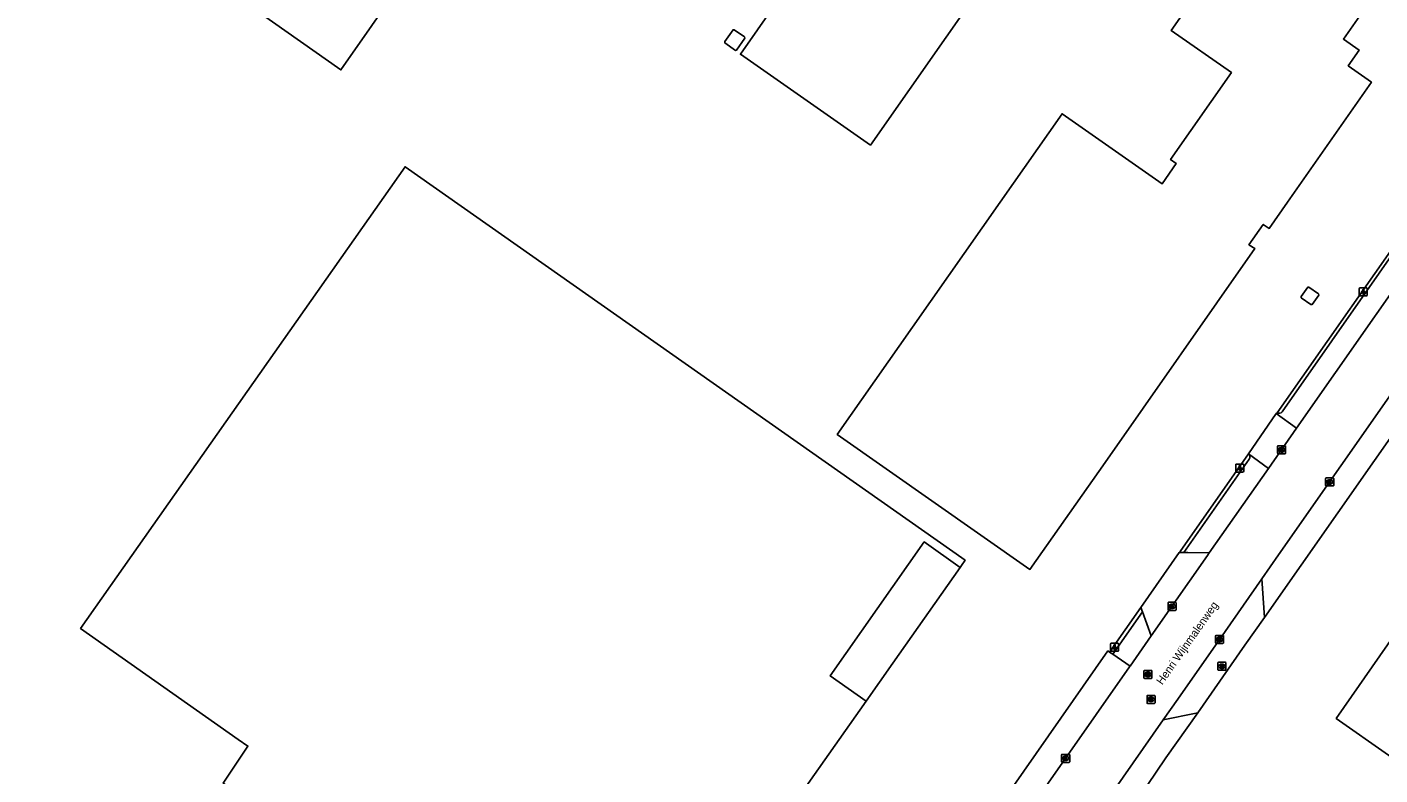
# Model space of a CAD drawing. Extents: x 155018 to 156648, y 383980 to 385733.
# Drawn here: x 155240.7 to 155409.7, y 384928.5 to 385021.9 of the extents above; entities that cross this region are included whole.
import ezdxf

# ---------------------------------------------------------------- set-up
doc = ezdxf.new("R2010")
doc.units = 0
for name, color, linetype in [('IMGEO_Brandkraan', 7, 'Continuous'), ('IMGEO_Hek', 7, 'Continuous'), ('IMGEO_Kolk', 7, 'Continuous'), ('IMGEO_Lichtpunt', 7, 'Continuous'), ('IMGEO_Openbare_ruimte_label', 7, 'Continuous'), ('IMGEO_Pand', 7, 'Continuous'), ('IMGEO_Pand_overbouw', 7, 'Continuous'), ('IMGEO_Parkeervlak_open', 7, 'Continuous'), ('IMGEO_Rijbaan_lokaal_gesloten', 7, 'Continuous'), ('IMGEO_Rijbaan_lokaal_open', 7, 'Continuous'), ('IMGEO_Rioolput', 7, 'Continuous'), ('IMGEO_Voetpad_open', 7, 'Continuous')]:
    doc.layers.add(name, color=color, linetype=linetype)

msp = doc.modelspace()

# ---------------------------------------------------------------- linework, layer by layer
at = {"layer": 'IMGEO_Brandkraan'}
for p, q in [((155389.49, 384941.61), (155389.49, 384942.47)), ((155389.56, 384942.54), (155390.42, 384942.54)), ((155389.98, 384942.32), (155390, 384942.32)), ((155390.49, 384942.47), (155390.49, 384941.61)), ((155390.42, 384941.54), (155389.56, 384941.54)), ((155390, 384941.76), (155389.98, 384941.76))]:
    msp.add_line(p, q, dxfattribs=at)
for points in [[(155389.49, 384941.61), (155389.49, 384942.47)], [(155389.56, 384942.54), (155390.42, 384942.54)], [(155389.84, 384942.24), (155389.84, 384941.84), (155390.05, 384941.84)], [(155390.07, 384942.24), (155389.84, 384942.24)], [(155390.02, 384942.16), (155389.96, 384942.16), (155389.96, 384942.08)], [(155389.96, 384942.08), (155390.02, 384942.08)], [(155390.03, 384942.01), (155389.96, 384942.01), (155389.96, 384941.92)], [(155389.96, 384941.92), (155390.03, 384941.92)], [(155390.49, 384942.47), (155390.49, 384941.61)], [(155390.42, 384941.54), (155389.56, 384941.54)]]:
    msp.add_lwpolyline(points, dxfattribs=at)
for centre, radius, start, end in [((155389.57, 384942.46), 0.0765, 91.552, 178.448), ((155389.57, 384942.46), 0.0765, 91.552, 178.448), ((155390.02, 384942.12), 0.0379, 267.8285, 90.9355), ((155390.03, 384941.97), 0.0404, 269.8759, 90.5077), ((155390.06, 384942.09), 0.251, 268.6676, 293.5347), ((155390.07, 384942.09), 0.145, 59.4692, 91.5367), ((155390.1, 384942.14), 0.0922, 285.5137, 58.1501), ((155390.1, 384941.95), 0.105, 301.3115, 78.989), ((155390.41, 384942.46), 0.0765, 1.552, 88.448), ((155390.41, 384942.46), 0.0765, 1.552, 88.448), ((155389.57, 384941.61), 0.0765, 181.552, 268.448), ((155389.57, 384941.61), 0.0765, 181.552, 268.448), ((155390.41, 384941.61), 0.0765, 271.552, 358.448), ((155390.41, 384941.61), 0.0765, 271.552, 358.448)]:
    msp.add_arc(centre, radius, start, end, dxfattribs=at)
for centre, major_axis, ratio, start_param, end_param in [((155389.98, 384942.04), (-0.387, 0.002), 0.722429, 4.712389, 7.853982), ((155390, 384942.04), (-0.39, 0.002), 0.717154, 1.570796, 4.712389)]:
    msp.add_ellipse(centre, major_axis=major_axis, ratio=ratio, start_param=start_param, end_param=end_param, dxfattribs=at)
at = {"layer": 'IMGEO_Hek'}
msp.add_lwpolyline([(155360.91, 384922.73), (155375.75, 384943.95)], dxfattribs=at)
at = {"layer": 'IMGEO_Kolk'}
for p, q in [((155396.95, 384968.65), (155396.95, 384969.5)), ((155397.02, 384969.57), (155397.87, 384969.57)), ((155397.43, 384969.35), (155397.46, 384969.35)), ((155397.95, 384969.5), (155397.95, 384968.65)), ((155397.87, 384968.57), (155397.02, 384968.57)), ((155397.46, 384968.79), (155397.43, 384968.79)), ((155402.94, 384964.63), (155402.94, 384965.48)), ((155403.02, 384965.56), (155403.87, 384965.56)), ((155403.95, 384965.48), (155403.95, 384964.63)), ((155403.87, 384964.56), (155403.02, 384964.56)), ((155403.43, 384965.34), (155403.46, 384965.34)), ((155403.45, 384964.78), (155403.43, 384964.78)), ((155383.26, 384949.1), (155383.26, 384949.95)), ((155383.33, 384950.03), (155384.18, 384950.03)), ((155384.18, 384949.02), (155383.33, 384949.02)), ((155383.74, 384949.8), (155383.77, 384949.8)), ((155383.77, 384949.25), (155383.74, 384949.25)), ((155384.26, 384949.95), (155384.26, 384949.1)), ((155389.2, 384944.96), (155389.2, 384945.81)), ((155389.27, 384945.89), (155390.12, 384945.89)), ((155389.69, 384945.67), (155389.71, 384945.67)), ((155390.2, 384945.81), (155390.2, 384944.96)), ((155390.12, 384944.89), (155389.27, 384944.89)), ((155389.71, 384945.11), (155389.68, 384945.11)), ((155369.96, 384930.12), (155369.96, 384930.97)), ((155370.04, 384931.04), (155370.89, 384931.04)), ((155370.89, 384930.04), (155370.04, 384930.04)), ((155370.45, 384930.82), (155370.48, 384930.82)), ((155370.47, 384930.26), (155370.45, 384930.26)), ((155370.97, 384930.97), (155370.97, 384930.12))]:
    msp.add_line(p, q, dxfattribs=at)
for points in [[(155396.95, 384968.65), (155396.95, 384969.5)], [(155397.02, 384969.57), (155397.87, 384969.57)], [(155397.27, 384969.27), (155397.39, 384969.27), (155397.39, 384969.12), (155397.52, 384969.27), (155397.68, 384969.27), (155397.54, 384969.12), (155397.69, 384968.87), (155397.54, 384968.87), (155397.45, 384969.04), (155397.39, 384968.97), (155397.39, 384968.87), (155397.27, 384968.87), (155397.27, 384969.27)], [(155397.95, 384969.5), (155397.95, 384968.65)], [(155397.87, 384968.57), (155397.02, 384968.57)], [(155402.94, 384964.63), (155402.94, 384965.48)], [(155403.02, 384965.56), (155403.87, 384965.56)], [(155403.95, 384965.48), (155403.95, 384964.63)], [(155403.87, 384964.56), (155403.02, 384964.56)], [(155403.26, 384965.26), (155403.39, 384965.26), (155403.39, 384965.11), (155403.52, 384965.26), (155403.68, 384965.26), (155403.54, 384965.11), (155403.69, 384964.86), (155403.54, 384964.86), (155403.45, 384965.02), (155403.39, 384964.96), (155403.39, 384964.86), (155403.26, 384964.86), (155403.26, 384965.26)], [(155383.26, 384949.1), (155383.26, 384949.95)], [(155383.33, 384950.03), (155384.18, 384950.03)], [(155384.18, 384949.02), (155383.33, 384949.02)], [(155383.58, 384949.72), (155383.7, 384949.72), (155383.7, 384949.57), (155383.83, 384949.72), (155383.99, 384949.72), (155383.85, 384949.57), (155384, 384949.32), (155383.85, 384949.32), (155383.76, 384949.49), (155383.7, 384949.42), (155383.7, 384949.32), (155383.58, 384949.32), (155383.58, 384949.72)], [(155384.26, 384949.95), (155384.26, 384949.1)], [(155389.2, 384944.96), (155389.2, 384945.81)], [(155389.27, 384945.89), (155390.12, 384945.89)], [(155389.52, 384945.59), (155389.64, 384945.59), (155389.64, 384945.44), (155389.77, 384945.59), (155389.94, 384945.59), (155389.79, 384945.44), (155389.94, 384945.19), (155389.79, 384945.19), (155389.71, 384945.35), (155389.64, 384945.29), (155389.64, 384945.19), (155389.52, 384945.19), (155389.52, 384945.59)], [(155390.2, 384945.81), (155390.2, 384944.96)], [(155390.12, 384944.89), (155389.27, 384944.89)], [(155369.96, 384930.12), (155369.96, 384930.97)], [(155370.04, 384931.04), (155370.89, 384931.04)], [(155370.89, 384930.04), (155370.04, 384930.04)], [(155370.28, 384930.74), (155370.41, 384930.74), (155370.41, 384930.59), (155370.54, 384930.74), (155370.7, 384930.74), (155370.56, 384930.59), (155370.71, 384930.34), (155370.56, 384930.34), (155370.47, 384930.51), (155370.41, 384930.44), (155370.41, 384930.34), (155370.28, 384930.34), (155370.28, 384930.74)], [(155370.97, 384930.97), (155370.97, 384930.12)]]:
    msp.add_lwpolyline(points, dxfattribs=at)
for centre, start, end in [((155397.02, 384969.5), 91.552, 178.448), ((155397.02, 384969.5), 91.552, 178.448), ((155397.87, 384969.5), 1.552, 88.448), ((155397.87, 384969.5), 1.552, 88.448), ((155397.02, 384968.65), 181.552, 268.448), ((155397.02, 384968.65), 181.552, 268.448), ((155397.87, 384968.65), 271.552, 358.448), ((155397.87, 384968.65), 271.552, 358.448), ((155403.02, 384965.48), 91.552, 178.448), ((155403.02, 384965.48), 91.552, 178.448), ((155403.87, 384965.48), 1.552, 88.448), ((155403.87, 384965.48), 1.552, 88.448), ((155403.02, 384964.63), 181.552, 268.448), ((155403.02, 384964.63), 181.552, 268.448), ((155403.87, 384964.63), 271.552, 358.448), ((155403.87, 384964.63), 271.552, 358.448), ((155383.33, 384949.95), 91.552, 178.448), ((155383.33, 384949.95), 91.552, 178.448), ((155383.33, 384949.1), 181.552, 268.448), ((155383.33, 384949.1), 181.552, 268.448), ((155384.18, 384949.95), 1.552, 88.448), ((155384.18, 384949.95), 1.552, 88.448), ((155384.18, 384949.1), 271.552, 358.448), ((155384.18, 384949.1), 271.552, 358.448), ((155389.27, 384945.81), 91.552, 178.448), ((155389.27, 384945.81), 91.552, 178.448), ((155390.12, 384945.81), 1.552, 88.448), ((155390.12, 384945.81), 1.552, 88.448), ((155389.27, 384944.96), 181.552, 268.448), ((155389.27, 384944.96), 181.552, 268.448), ((155390.12, 384944.96), 271.552, 358.448), ((155390.12, 384944.96), 271.552, 358.448), ((155370.04, 384930.97), 91.552, 178.448), ((155370.04, 384930.97), 91.552, 178.448), ((155370.04, 384930.12), 181.552, 268.448), ((155370.04, 384930.12), 181.552, 268.448), ((155370.89, 384930.97), 1.552, 88.448), ((155370.89, 384930.97), 1.552, 88.448), ((155370.89, 384930.12), 271.552, 358.448), ((155370.89, 384930.12), 271.552, 358.448)]:
    msp.add_arc(centre, 0.0765, start, end, dxfattribs=at)
for centre, major_axis, ratio, start_param, end_param in [((155397.43, 384969.07), (-0.387, 0.002), 0.722429, 4.712389, 7.853982), ((155397.46, 384969.07), (-0.39, 0.002), 0.717154, 1.570796, 4.712389), ((155403.43, 384965.06), (-0.387, 0.002), 0.722429, 4.712389, 7.853982), ((155403.46, 384965.06), (-0.39, 0.002), 0.717154, 1.570796, 4.712389), ((155383.74, 384949.52), (-0.387, 0.002), 0.722429, 4.712389, 7.853982), ((155383.77, 384949.52), (-0.39, 0.002), 0.717154, 1.570796, 4.712389), ((155389.68, 384945.39), (-0.387, 0.002), 0.722429, 4.712389, 7.853982), ((155389.71, 384945.39), (-0.39, 0.002), 0.717154, 1.570796, 4.712389), ((155370.45, 384930.54), (-0.387, 0.002), 0.722429, 4.712389, 7.853982), ((155370.48, 384930.54), (-0.39, 0.002), 0.717154, 1.570796, 4.712389)]:
    msp.add_ellipse(centre, major_axis=major_axis, ratio=ratio, start_param=start_param, end_param=end_param, dxfattribs=at)
at = {"layer": 'IMGEO_Lichtpunt'}
for p, q in [((155407.15, 384989.2), (155407.15, 384988.4)), ((155407.15, 384989.2), (155407.15, 384988.4)), ((155408.05, 384989.3), (155407.24, 384989.3)), ((155408.05, 384989.3), (155407.24, 384989.3)), ((155408.14, 384988.4), (155408.14, 384989.2)), ((155408.14, 384988.4), (155408.14, 384989.2)), ((155407.24, 384988.3), (155408.05, 384988.3)), ((155407.24, 384988.3), (155408.05, 384988.3)), ((155391.72, 384967.2), (155391.72, 384966.4)), ((155391.72, 384967.2), (155391.72, 384966.4)), ((155392.62, 384967.3), (155391.81, 384967.3)), ((155392.62, 384967.3), (155391.81, 384967.3)), ((155392.71, 384966.4), (155392.71, 384967.2)), ((155392.71, 384966.4), (155392.71, 384967.2)), ((155391.81, 384966.3), (155392.62, 384966.3)), ((155391.81, 384966.3), (155392.62, 384966.3)), ((155376.07, 384944.82), (155376.07, 384944.01)), ((155376.07, 384944.82), (155376.07, 384944.01)), ((155376.97, 384944.91), (155376.17, 384944.91)), ((155376.97, 384944.91), (155376.17, 384944.91)), ((155376.17, 384943.91), (155376.97, 384943.91)), ((155376.17, 384943.91), (155376.97, 384943.91)), ((155377.07, 384944.01), (155377.07, 384944.82)), ((155377.07, 384944.01), (155377.07, 384944.82))]:
    msp.add_line(p, q, dxfattribs=at)
for points in [[(155407.52, 384988.87), (155407.56, 384988.84), (155407.37, 384988.58), (155407.33, 384988.61), (155407.52, 384988.87)], [(155407.62, 384988.82), (155407.67, 384988.82), (155407.67, 384988.5), (155407.62, 384988.5), (155407.62, 384988.82)], [(155407.73, 384988.84), (155407.77, 384988.87), (155407.96, 384988.6), (155407.92, 384988.58), (155407.73, 384988.84)], [(155392.09, 384966.87), (155392.13, 384966.84), (155391.94, 384966.58), (155391.9, 384966.61), (155392.09, 384966.87)], [(155392.19, 384966.82), (155392.24, 384966.82), (155392.24, 384966.5), (155392.19, 384966.5), (155392.19, 384966.82)], [(155392.3, 384966.84), (155392.34, 384966.87), (155392.53, 384966.6), (155392.49, 384966.58), (155392.3, 384966.84)], [(155376.45, 384944.48), (155376.48, 384944.45), (155376.3, 384944.19), (155376.26, 384944.22), (155376.45, 384944.48)], [(155376.55, 384944.43), (155376.59, 384944.43), (155376.59, 384944.11), (155376.55, 384944.11), (155376.55, 384944.43)], [(155376.66, 384944.45), (155376.7, 384944.48), (155376.88, 384944.22), (155376.84, 384944.19), (155376.66, 384944.45)]]:
    msp.add_lwpolyline(points, dxfattribs=at)
for centre in [(155407.65, 384989), (155392.22, 384967), (155376.57, 384944.61)]:
    msp.add_circle(centre, 0.0994, dxfattribs=at)
for centre, start, end in [((155407.24, 384989.2), 90, 180), ((155407.24, 384989.2), 90, 180), ((155408.05, 384989.2), 0, 90), ((155408.05, 384989.2), 0, 90), ((155407.24, 384988.4), 180, 270), ((155407.24, 384988.4), 180, 270), ((155408.05, 384988.4), 270, 0), ((155408.05, 384988.4), 270, 360), ((155391.81, 384967.2), 90, 180), ((155391.81, 384967.2), 90, 180), ((155392.62, 384967.2), 0, 90), ((155392.62, 384967.2), 0, 90), ((155391.81, 384966.4), 180, 270), ((155391.81, 384966.4), 180, 270), ((155392.62, 384966.4), 270, 0), ((155392.62, 384966.4), 270, 360), ((155376.17, 384944.82), 90, 180), ((155376.17, 384944.82), 90, 180), ((155376.17, 384944.01), 180, 270), ((155376.17, 384944.01), 180, 270), ((155376.97, 384944.82), 0, 90), ((155376.97, 384944.82), 0, 90), ((155376.97, 384944.01), 270, 0), ((155376.97, 384944.01), 270, 360)]:
    msp.add_arc(centre, 0.0946, start, end, dxfattribs=at)
at = {"layer": 'IMGEO_Pand'}
for points in [[(155360.4, 385027.59), (155371.25, 385043.14), (155373.67, 385046.6), (155373.68, 385046.71), (155374.05, 385047.29), (155357.87, 385058.61), (155357.47, 385058.02), (155335.4, 385073.46), (155332.53, 385069.36), (155322.01, 385054.44), (155322.2, 385054.3), (155344.14, 385038.95), (155329.83, 385018.48), (155346.07, 385007.13), (155360.4, 385027.59)], [(155240.71, 385044.07), (155279.93, 385016.52), (155291.83, 385033.6)], [(155392.24, 385033.74), (155383.64, 385021.45), (155391.17, 385016.18), (155383.58, 385005.33), (155384.29, 385004.83), (155382.52, 385002.29), (155370.02, 385011.04), (155362.29, 385000), (155351.35, 384984.37), (155341.94, 384971), (155365.99, 384954.13), (155375.42, 384967.49), (155394.1, 384994.2), (155393.37, 384994.69), (155395.14, 384997.23), (155395.89, 384996.73), (155398.18, 385000), (155408.66, 385014.97), (155405.76, 385017.03), (155407.12, 385018.99), (155405.17, 385020.37), (155407.2, 385023.27), (155392.24, 385033.74)], [(155329.34, 385019), (155329.2, 385018.96), (155327.9, 385019.9), (155327.88, 385020.05), (155328.92, 385021.53), (155329.07, 385021.54), (155330.36, 385020.63), (155330.4, 385020.49), (155329.34, 385019)], [(155345.56, 384937.67), (155341.06, 384940.84), (155352.79, 384957.57), (155357.29, 384954.38), (155357.45, 384954.61), (155357.9, 384955.28), (155287.95, 385004.43), (155247.39, 384946.76), (155267.07, 384932.91), (155268.31, 384932.07), (155265.22, 384927.44), (155312.84, 384894.01), (155325.53, 384911.73), (155326.66, 384910.93), (155345.56, 384937.67)], [(155437.27, 384901.4), (155412.16, 384919.02), (155417.32, 384926.36), (155404.26, 384935.52), (155429.93, 384972.31), (155422.84, 384977.26), (155438.82, 385000), (155439.82, 385001.42), (155441.82, 385000), (155445.21, 384997.6), (155444.28, 384997.18), (155444.97, 384993.26), (155452.4, 384994.45), (155452.45, 384994.1), (155450.71, 384993.78), (155463.95, 384984.47), (155458.94, 384977.31), (155471.07, 384968.79), (155464.08, 384958.83), (155473.16, 384952.46), (155437.27, 384901.4)], [(155399.9, 384988.06), (155399.87, 384988.22), (155400.71, 384989.38), (155400.86, 384989.4), (155402.05, 384988.54), (155402.08, 384988.4), (155401.27, 384987.23), (155401.11, 384987.23), (155399.9, 384988.06)]]:
    msp.add_lwpolyline(points, dxfattribs=at)
at = {"layer": 'IMGEO_Pand_overbouw'}
msp.add_lwpolyline([(155357.29, 384954.38), (155352.79, 384957.57), (155341.06, 384940.84), (155345.56, 384937.67), (155348.89, 384942.41)], close=True, dxfattribs=at)
at = {"layer": 'IMGEO_Parkeervlak_open'}
msp.add_lwpolyline([(155396.77, 384973.59), (155396.87, 384973.7)], dxfattribs=at)
at = {"layer": 'IMGEO_Rijbaan_lokaal_gesloten'}
for points in [[(155425.67, 385009.38), (155419.1, 385000), (155399.32, 384971.77)], [(155394.96, 384952.94), (155397.07, 384955.96), (155427.93, 385000), (155432.19, 385006.09)], [(155395.81, 384966.75), (155399.32, 384971.77)], [(155388.41, 384956.19), (155395.81, 384966.75)], [(155381.16, 384945.84), (155388.18, 384955.86), (155388.41, 384956.19)], [(155394.96, 384952.94), (155390.39, 384946.37), (155384.46, 384937.95), (155382.66, 384935.36)], [(155381.16, 384945.84), (155378.52, 384942.07)], [(155361.77, 384918.15), (155378.44, 384941.96), (155378.52, 384942.07)], [(155382.66, 384935.36), (155376.39, 384926.39), (155374.74, 384924.03)]]:
    msp.add_lwpolyline(points, dxfattribs=at)
at = {"layer": 'IMGEO_Rijbaan_lokaal_open'}
for points in [[(155396.77, 384973.59), (155393.3, 384968.59)], [(155399.32, 384971.77), (155396.77, 384973.59)], [(155395.81, 384966.75), (155393.3, 384968.59)], [(155384.65, 384956.24), (155379.85, 384949.39)], [(155385.23, 384956.23), (155384.65, 384956.24)], [(155388.41, 384956.19), (155385.73, 384956.23), (155385.23, 384956.23)], [(155395.3, 384948.12), (155394.96, 384952.94)], [(155379.85, 384949.39), (155380.05, 384948.85)], [(155380.05, 384948.85), (155381.16, 384945.84)], [(155386.96, 384936.21), (155392.87, 384944.66), (155395.3, 384948.12)], [(155375.95, 384943.82), (155375.75, 384943.95), (155360.92, 384922.73)], [(155376.36, 384943.56), (155375.95, 384943.82)], [(155378.52, 384942.07), (155376.36, 384943.56)], [(155386.96, 384936.21), (155386.78, 384936.17), (155382.66, 384935.36)]]:
    msp.add_lwpolyline(points, dxfattribs=at)
at = {"layer": 'IMGEO_Rioolput'}
for p, q in [((155380.25, 384940.6), (155380.25, 384941.45)), ((155380.32, 384941.52), (155381.17, 384941.52)), ((155381.17, 384940.52), (155380.32, 384940.52)), ((155380.76, 384940.74), (155380.73, 384940.74)), ((155380.74, 384941.3), (155380.76, 384941.3)), ((155381.25, 384941.45), (155381.25, 384940.6)), ((155380.63, 384937.48), (155380.63, 384938.33)), ((155380.7, 384938.41), (155381.55, 384938.41)), ((155381.55, 384937.41), (155380.7, 384937.41)), ((155381.11, 384938.19), (155381.14, 384938.19)), ((155381.14, 384937.63), (155381.11, 384937.63)), ((155381.63, 384938.33), (155381.63, 384937.48))]:
    msp.add_line(p, q, dxfattribs=at)
for points in [[(155380.25, 384940.6), (155380.25, 384941.45)], [(155380.32, 384941.52), (155381.17, 384941.52)], [(155381.17, 384940.52), (155380.32, 384940.52)], [(155380.84, 384941.22), (155380.58, 384941.22), (155380.58, 384940.82)], [(155380.58, 384940.82), (155380.71, 384940.82), (155380.71, 384940.99), (155380.72, 384940.99)], [(155380.76, 384941.14), (155380.71, 384941.14), (155380.71, 384941.06)], [(155380.71, 384941.06), (155380.76, 384941.06)], [(155380.77, 384940.96), (155380.84, 384940.82), (155380.98, 384940.82), (155380.91, 384940.95)], [(155381.25, 384941.45), (155381.25, 384940.6)], [(155380.63, 384937.48), (155380.63, 384938.33)], [(155380.7, 384938.41), (155381.55, 384938.41)], [(155381.55, 384937.41), (155380.7, 384937.41)], [(155381.21, 384938.11), (155380.96, 384938.11), (155380.96, 384937.71)], [(155380.96, 384937.71), (155381.09, 384937.71), (155381.09, 384937.87), (155381.1, 384937.87)], [(155381.14, 384938.03), (155381.09, 384938.03), (155381.09, 384937.95)], [(155381.09, 384937.95), (155381.14, 384937.95)], [(155381.14, 384937.84), (155381.22, 384937.71), (155381.35, 384937.71), (155381.29, 384937.83)], [(155381.63, 384938.33), (155381.63, 384937.48)]]:
    msp.add_lwpolyline(points, dxfattribs=at)
for centre, radius, start, end in [((155380.32, 384941.45), 0.0765, 91.552, 178.448), ((155380.32, 384941.45), 0.0765, 91.552, 178.448), ((155380.32, 384940.6), 0.0765, 181.552, 268.448), ((155380.32, 384940.6), 0.0765, 181.552, 268.448), ((155380.72, 384940.93), 0.0533, 26.0293, 88.6989), ((155380.77, 384941.05), 0.0964, 77.0061, 93.1865), ((155380.74, 384941.25), 0.19, 274.7715, 282.9687), ((155380.78, 384941.1), 0.0378, 276.6634, 79.6772), ((155380.84, 384941.11), 0.109, 350.3612, 89.416), ((155380.83, 384941.11), 0.112, 277.5842, 350.9817), ((155380.82, 384940.9), 0.108, 29.5134, 73.7905), ((155381.17, 384941.45), 0.0765, 1.552, 88.448), ((155381.17, 384941.45), 0.0765, 1.552, 88.448), ((155381.17, 384940.6), 0.0765, 271.552, 358.448), ((155381.17, 384940.6), 0.0765, 271.552, 358.448), ((155380.7, 384938.33), 0.0765, 91.552, 178.448), ((155380.7, 384938.33), 0.0765, 91.552, 178.448), ((155380.7, 384937.48), 0.0765, 181.552, 268.448), ((155380.7, 384937.48), 0.0765, 181.552, 268.448), ((155381.1, 384937.82), 0.0533, 26.0293, 88.6989), ((155381.15, 384937.93), 0.0964, 77.0061, 93.1865), ((155381.12, 384938.14), 0.19, 274.7715, 282.9687), ((155381.16, 384937.99), 0.0378, 276.6634, 79.6772), ((155381.21, 384938), 0.109, 350.3612, 89.416), ((155381.21, 384938), 0.112, 277.5842, 350.9817), ((155381.2, 384937.78), 0.108, 29.5134, 73.7905), ((155381.55, 384938.33), 0.0765, 1.552, 88.448), ((155381.55, 384938.33), 0.0765, 1.552, 88.448), ((155381.55, 384937.48), 0.0765, 271.552, 358.448), ((155381.55, 384937.48), 0.0765, 271.552, 358.448)]:
    msp.add_arc(centre, radius, start, end, dxfattribs=at)
for centre, major_axis, ratio, start_param, end_param in [((155380.73, 384941.02), (-0.387, 0.002), 0.722429, 4.712389, 7.853982), ((155380.76, 384941.02), (-0.39, 0.002), 0.717154, 1.570796, 4.712389), ((155381.11, 384937.91), (-0.387, 0.002), 0.722429, 4.712389, 7.853982), ((155381.14, 384937.91), (-0.39, 0.002), 0.717154, 1.570796, 4.712389)]:
    msp.add_ellipse(centre, major_axis=major_axis, ratio=ratio, start_param=start_param, end_param=end_param, dxfattribs=at)
at = {"layer": 'IMGEO_Voetpad_open'}
for points in [[(155396.87, 384973.7), (155415.32, 385000), (155424.16, 385012.6)], [(155422.68, 385009.78), (155415.83, 385000), (155397.52, 384973.82)], [(155435.24, 385005.1), (155431.66, 385000), (155395.3, 384948.12)], [(155393.3, 384968.59), (155384.75, 384956.38), (155384.65, 384956.24)], [(155393.39, 384967.91), (155385.23, 384956.23)], [(155375.95, 384943.82), (155379.85, 384949.39)], [(155380.05, 384948.85), (155376.36, 384943.56)], [(155376.2, 384920.8), (155378, 384923.37), (155380.63, 384927.15), (155382.99, 384930.59), (155386.96, 384936.21)]]:
    msp.add_lwpolyline(points, dxfattribs=at)
for centre, start, end in [((155397.13, 384974.12), 237.5709, 322.3244), ((155393, 384968.2), 322.7419, 51.9416)]:
    msp.add_arc(centre, 0.49, start, end, dxfattribs=at)

# ---------------------------------------------------------------- texts
at = {"layer": 'IMGEO_Openbare_ruimte_label'}
msp.add_text('Henri Wijnmalenweg', height=1, rotation=54.8953, dxfattribs=at).set_placement((155382.53, 384939.65))

doc.saveas('drawing.dxf')
